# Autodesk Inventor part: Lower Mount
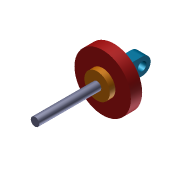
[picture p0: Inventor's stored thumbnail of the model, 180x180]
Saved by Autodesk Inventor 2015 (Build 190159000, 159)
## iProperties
Created: 2020-09
Part Number: Lower Mount
Material: 一般
Document SubType Name: Modeling
Designer: 徐冠倫
Mass: 238.957 g
Surface Area: 352.269 cm^2
Volume: 238.957 cm^3
Density: 1 g/cm^3
Appearance: 預設
Author: 徐冠倫
Author: IANNIAN
Title: D:\Desktop\OCW-Computer-Aided Engineering Drawing\OCW_Topic 06：組合圖與機構模擬(進階)\Shock Absorber\Lower-STP.stp
Creation Date: 2020-08-21
Sending System: Autodesk Inventor 2020
Preprocessor: ST-DEVELOPER v18
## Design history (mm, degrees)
node "Lower-STP1"
body "Solid1"
node "Base1"
